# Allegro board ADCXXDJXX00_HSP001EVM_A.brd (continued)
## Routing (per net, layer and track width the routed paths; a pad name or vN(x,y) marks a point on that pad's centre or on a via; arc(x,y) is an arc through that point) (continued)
LMK_LMX_DATA: length 169.4
  TOP w0.279: R119.2 69.34,37.85 69.98,37.21 69.98,29.97 71.37,28.57 77.09,28.57 v1(78.87,30.35)
  L04_SIG-1 w0.14: v1(99.67,94.05) 99.67,92.89 95.43,88.65 85.71,88.65 77.64,96.72 77.64,102.46 68.7,111.4 62.23,111.4 61.32,112.32 v1(61.32,112.89)
  L10_SIG-2 w0.165: v1(61.32,112.89) 61.43,113 62.2,113 62.48,112.72 62.48,112.19 64.73,109.94 64.73,59.02 72.17,51.59 72.17,37.05 v1(78.87,30.35)
  BOTTOM w0.279: U4.20 100.32,97.93 100.32,94.7 v1(99.67,94.05) ; v1(61.32,112.89) 61.3,112.9 U3.17
LMK_SDO: length 119.2
  TOP w0.279: v1(107.44,47.24) 100.84,47.24 94.23,40.64 94.23,35.21 92.78,33.76 75.24,33.76 72.24,36.77 72.24,40.22 70.35,42.11 67,42.11 66.67,41.78 R178.2
  L10_SIG-2 w0.165: v1(104.75,103.96) 104.75,103.22 105.54,102.43 105.54,96.99 105.06,96.51 103.25,96.51 102.65,95.9 102.65,58.34 105.08,55.91 105.08,49.61 v1(107.44,47.24)
  BOTTOM w0.279: U4.5 104.4,104.31 v1(104.75,103.96)
LMX_CLKB: length 27.1
  L04_SIG-1 w0.14: v1(79.48,97.23) 79.78,97.53 v1(79.78,103.42)
  BOTTOM w0.279: C108.2 R52.2 64.32,109.21 69.75,103.78 76.58,103.78 76.94,103.42 v1(79.78,103.42)
LMX_CLKM: length 73.9
  BOTTOM w0.254: C51.1 24.42,72.92 24.85,72.92 arc(25.64,73.25) 25.97,74.04 25.97,74.59 arc(25.8,75.44) 25.32,76.16 23.26,78.21 arc(22.78,78.93) 22.61,79.78 22.61,93.37 arc(23.36,95.17) 25.15,95.91 44.69,95.91 arc(45.91,96.15) 46.94,96.84 53.13,103.03 arc(54.58,105.2) 55.09,107.76 55.09,113.91 arc(55.42,114.7) 56.21,115.03 56.72,115.03 R45.1 57.34,114.88 arc(57.49,114.91) 57.61,114.99 arc(57.77,115.1) 57.96,115.14 U3.22
LMX_CLKP: length 73.9
  BOTTOM w0.254: U3.23 57.98,115.64 arc(57.77,115.68) 57.6,115.79 arc(57.49,115.87) 57.35,115.89 R44.1 56.72,115.74 56.21,115.74 arc(54.91,115.21) 54.38,113.91 54.38,107.76 arc(53.92,105.47) 52.63,103.53 46.44,97.35 arc(45.64,96.81) 44.69,96.62 25.15,96.62 arc(22.85,95.67) 21.9,93.37 21.9,79.78 arc(22.13,78.66) 22.76,77.71 24.81,75.65 arc(25.14,75.16) 25.26,74.59 25.26,74.04 arc(25.14,73.75) 24.85,73.63 24.42,73.63 C50.1
LMX_CSB: length 109.9
  TOP w0.279: v1(79.2,33.03) 75.1,33.03 71.81,36.32 71.81,39.32 R121.2
  L10_SIG-2 w0.165: v1(79.2,33.03) 79.16,33.03 78.2,33.99 78.2,52.52 65.97,64.75 65.97,108 66.65,108.67 66.65,113.19 65.54,114.29 60.13,114.29 v1(58.02,116.4)
  BOTTOM w0.127: U3.24 58.28,116.14 v1(58.02,116.4)
LMX_OSCM: length 46.8
  L10_SIG-2 w0.16: v4(96.88,92.46) 96.83,92.42 96.83,91.76 arc(96.4,90.72) 95.36,90.29 91.46,90.29 arc(89.09,90.76) 87.08,92.1 85.93,93.25 85.88,93.3 85.41,93.77 85.32,93.86 84.83,94.35 84.77,94.41 84.29,94.89 84.04,95.15 83.73,95.45 83.13,96.05 74.19,104.99 74.06,105.12 73.54,105.64 73.48,105.71 73.09,106.09 arc(72.46,107.03) 72.24,108.15 72.24,109.08 arc(72.06,110.01) 71.53,110.79 69.67,112.65 v4(69.61,112.65)
  BOTTOM w0.254: v4(96.88,92.46) 96.85,92.49 96.85,94.36 C151.2 ; U3.9 66.1,115.14 arc(66.27,115.1) 66.41,115.01 arc(66.5,114.95) 66.61,114.92 66.82,114.92 arc(67.33,114.82) 67.76,114.54 69.61,112.69 v4(69.61,112.65)
LMX_OSCP: length 47.3
  L10_SIG-2 w0.16: v4(70.14,113.19) 70.14,113.13 72.01,111.26 arc(72.68,110.26) 72.91,109.08 72.91,108.15 arc(73.08,107.29) 73.57,106.56 73.73,106.4 arc(73.83,106.34) 73.95,106.31 74.3,106.31 arc(74.4,106.29) 74.49,106.24 74.68,106.05 arc(74.74,105.96) 74.76,105.85 74.76,105.5 arc(74.78,105.38) 74.85,105.28 82.96,97.17 arc(83.14,97.05) 83.36,97 83.55,97 arc(83.77,96.96) 83.96,96.84 83.96,96.83 arc(84.11,96.61) 84.17,96.34 84.17,96.16 arc(84.19,96.03) 84.27,95.91 84.41,95.77 arc(84.5,95.71) 84.61,95.69 84.84,95.69 arc(85.04,95.65) 85.2,95.53 85.2,95.53 arc(85.34,95.32) 85.39,95.08 85.39,94.88 arc(85.42,94.75) 85.49,94.64 85.62,94.51 arc(85.73,94.43) 85.86,94.41 86.06,94.41 arc(86.31,94.36) 86.52,94.21 86.57,94.17 arc(86.69,93.98) 86.74,93.77 86.74,93.48 arc(86.75,93.4) 86.8,93.33 87.56,92.57 arc(89.35,91.38) 91.46,90.96 91.94,90.96 arc(92.05,90.98) 92.15,91.04 92.24,91.14 arc(92.46,91.29) 92.72,91.34 92.72,91.34 arc(92.96,91.29) 93.17,91.15 93.29,91.04 arc(93.37,90.98) 93.47,90.96 93.72,90.96 arc(93.82,90.98) 93.91,91.04 93.92,91.05 94.03,91.16 arc(94.19,91.27) 94.39,91.31 arc(94.6,91.27) 94.78,91.15 94.9,91.03 arc(94.97,90.98) 95.07,90.96 95.36,90.96 arc(95.93,91.19) 96.16,91.76 96.16,92.42 v4(96.12,92.46)
  BOTTOM w0.254: v4(70.14,113.19) 70.11,113.19 68.26,115.04 arc(67.6,115.48) 66.82,115.64 U3.8 ; C250.1 96.14,94.36 96.14,92.49 v4(96.12,92.46)
LMX_SDO: length 118
  TOP w0.279: U8.43 v1(66.4,40.37)
  L10_SIG-2 w0.165: v1(78.78,31.79) 76.97,33.6 76.97,40.28 75.99,41.26 75.99,49.44 65.41,60.03 65.41,113.02 64.62,113.8 60.47,113.8 59.77,113.1 58.02,113.1 v1(56.72,111.81)
  BOTTOM w0.279: v1(78.78,31.79) 75.32,31.79 72.62,34.49 67.61,34.49 66.4,35.71 v1(66.4,40.37)
MUX_OUT: length 35.5
  TOP w0.279: v1(57.74,111.81) 57.74,111.08 57.46,110.8 56.76,110.8 56.24,111.32 50.05,111.32 48.56,112.81 48.56,122.49 49.72,123.66 57.87,123.66 v1(59.16,122.37)
  BOTTOM w0.254: R50.2 v1(59.16,122.37)
  BOTTOM w0.279: U3.20 57.75,111.81 v1(57.74,111.81)
NCOA0: length 178.5
  TOP w0.279: R11.1 v1(87.37,40.04)
  L04_SIG-1 w0.102: v1(35.33,76.08) 34.93,75.69 33.55,75.69 33.33,75.91 33.33,77.28
  L04_SIG-1 w0.14: v1(76.05,94.3) 72.13,90.39 56.32,90.39 53.67,93.03 53.67,94.27 45.95,102 45.95,110.45 48.74,113.25 48.74,119.83 J7.2 45.62,120.52 41.51,120.52 40.52,119.53 40.52,112.64 34.22,106.34 32.37,106.34 30.56,104.53 30.56,98.18 32.85,95.89 32.85,79.97 33.33,79.49 33.33,77.28
  L10_SIG-2 w0.165: v1(87.37,40.04) 83.72,43.69 83.72,86.63 v1(76.05,94.3)
NCOA1: length 169.7
  TOP w0.279: R12.1 v1(87.37,38.9)
  L04_SIG-1 w0.102: 34.11,77.44 34.11,76.68 34.3,76.49 35.49,76.49 35.72,76.26 35.72,75.9 35.33,75.5 v1(35.33,75.28)
  L04_SIG-1 w0.14: v1(45.03,79.73) 45.09,79.73 47.03,77.79 47.03,49.53 v1(46.38,48.89) ; 34.11,77.44 34.11,79.44 33.43,80.13 33.43,86.51 34.2,87.27 34.2,88.39 33.45,89.14 33.45,96.45 31.28,98.62 31.28,103.58 32.73,105.03 35.52,105.03 42.75,112.26 42.75,117.08 43.75,118.08 45.73,118.08 J7.4
  L10_SIG-2 w0.102: 34.13,78.21 34.13,75.05 34.29,74.9 34.94,74.9 v1(35.33,75.28)
  L10_SIG-2 w0.165: 34.13,78.21 34.13,78.44 34.04,78.54 34.04,80.24 35.94,82.14 41.22,82.14 43.63,79.73 v1(45.03,79.73)
  BOTTOM w0.279: v1(46.38,48.89) 50.02,52.52 56.64,52.52 57.09,52.97 60.25,52.97 60.7,52.52 89.4,52.52 91.03,50.9 91.03,42.56 v1(87.37,38.9)
NCOB0: length 157.1
  TOP w0.279: R17.1 v1(87.37,37.76)
  L10_SIG-2 w0.102: v1(35.33,70.48) 34.92,70.88 31.94,70.88 31.73,71.09 31.73,77.3 31.56,77.47
  L10_SIG-2 w0.165: 31.56,77.47 31.51,77.52 31.51,78.14 31.98,78.61 31.98,82.42 35.52,85.96 42.38,85.96 45.16,88.73 45.16,101.38 43.96,102.58 43.96,110.8 45.57,112.41 45.57,115.39 J7.6
  BOTTOM w0.279: v1(35.33,70.48) 34.7,69.85 34.7,69.82 34.48,69.6 34.43,69.6 33.83,69 33.83,68.37 34.29,67.91 34.29,61.5 33.21,60.42 33.21,53.46 36.92,49.75 42.55,49.75 44.78,47.52 48.3,47.52 49.87,49.09 53.17,49.09 55.72,51.65 56.98,51.65 57.47,52.14 59.88,52.14 60.37,51.65 89.49,51.65 90.26,50.88 90.26,43.75 86.71,40.2 86.71,38.41 v1(87.37,37.76)
NCOB1: length 166
  TOP w0.279: R18.1 v1(87.37,36.61)
  L10_SIG-2 w0.089: 32.54,77.47 32.53,77.46
  L10_SIG-2 w0.102: v1(35.33,71.28) 34.93,71.68 32.73,71.68 32.53,71.87 32.53,77.25
  L10_SIG-2 w0.165: J7.8 46.84,110.99 45.6,109.75 45.6,105.64 46.86,104.38 46.86,88.99 41.59,83.72 34.16,83.72 32.84,82.4 32.84,77.76 32.54,77.47 ; 32.53,77.46 32.53,77.25
  BOTTOM w0.127: v1(35.33,71.28) 35.27,71.28 34.88,70.88 32.67,70.88 32.52,70.74 32.52,70.32 32.29,70.09 30.8,70.09 30.52,69.8
  BOTTOM w0.279: v1(87.37,36.61) 85.75,38.23 85.75,40.36 87.31,41.92 87.31,46.7 85.45,48.55 76.48,48.55 74.48,50.55 55.79,50.55 51.93,46.68 44.22,46.68 42.91,48 28.63,48 24.88,51.75 24.88,55.83 22.25,58.46 22.25,61.7 25.04,64.48 25.04,65.02 26.61,66.59 28.2,66.59 28.76,67.14 28.76,68.04 30.52,69.8
OSC_M: length 17.6
  L04_SIG-1 w0.124: v1(95.55,94.45) 96.15,94.45 96.41,94.71 96.41,96.17 93.6,98.99 90.27,98.99 89.3,99.96 89.3,101.68 90.35,102.72 91.25,102.72 v2(91.47,102.94)
  BOTTOM w0.152: U4.41 92.71,102.81 92.6,102.7 91.71,102.7 v2(91.47,102.94)
OSC_P: length 17.7
  L04_SIG-1 w0.124: v2(91.47,102.18) 91.23,102.41 90.47,102.41 89.61,101.55 89.61,100.09 90.4,99.29 93.72,99.29 94.32,98.69 94.68,98.69 94.84,98.53 94.84,98.18 95.15,97.87 95.51,97.87 95.67,97.72 95.67,97.35 95.97,97.05 96.33,97.05 96.49,96.89 96.49,96.53 96.72,96.3 96.72,94.71 97.05,94.38 v1(97.49,94.38)
  BOTTOM w0.152: v2(91.47,102.18) 91.71,102.42 92.6,102.42 92.71,102.31 U4.40
OSCI: length 8.4
  TOP w0.152: Y2.2 50.78,44.6 C184.1 50.8,42.85 50.95,42.7 51.56,42.7 51.71,42.85 52.84,42.85 53.41,42.27 53.63,42.27 53.73,42.37 U8.2
OSCINN: length 4.5
  BOTTOM w0.152: C150.2 89.11,104.39 C152.2 90.1,104.39 90.29,104.2 92.6,104.2 92.71,104.31 U4.44
OSCINP: length 4.5
  BOTTOM w0.152: C145.2 89.11,103.73 C146.2 90.1,103.73 90.29,103.92 92.6,103.92 92.71,103.81 U4.43
OSCN: length 2.4
  BOTTOM w0.152: C149.2 86.21,104.39 R88.2 R93.1 87.78,104.44 C150.1
OSCO: length 8.4
  TOP w0.152: Y2.1 50.78,40.49 50.8,40.51 50.8,42.24 50.98,42.42 51.68,42.42 51.83,42.57 52.72,42.57 53.3,41.99 53.61,41.99 53.73,41.87 U8.3
OSCP: length 2.3
  BOTTOM w0.152: C144.2 86.16,103.73 R82.2 R85.1 87.78,103.68 C145.1
OVRA0: length 198.7
  TOP w0.279: v1(95.63,34.8) 95.58,34.85 D12.1 ; v1(55.03,95.67) 54.99,95.63 35.21,95.63 v1(31.75,92.17)
  L04_SIG-1 w0.089: v1(36.12,76.08) 36.12,75.9 35.7,75.48 35.7,75.07 35.49,74.85 32.72,74.85 32.51,75.07 32.51,77.26 32.67,77.42 32.67,77.47
  L04_SIG-1 w0.14: 32.67,77.47 32.67,78.43 32.26,78.84 32.26,86.66 31.75,87.17 v1(31.75,92.17) ; v1(135.25,55.37) 134.36,54.48 131.81,54.48 129.37,52.04 120.82,52.04 119.01,50.23 116.9,50.23 101.47,34.8 v1(95.63,34.8) 95.63,48.87 94.73,49.78 v1(91.71,49.78) 91.27,50.22 91.27,51.92 88.33,54.85 62.88,54.85 v1(59.63,51.6)
  L10_SIG-2 w0.165: v1(55.03,95.67) 55.03,65.33 59.63,60.73 v1(59.63,51.6)
OVRA1: length 116
  L04_SIG-1 w0.14: v1(52.46,94.64) 52.41,94.58 52.41,90.56 v1(41.44,79.59) ; v1(91.71,48.64) 90.43,49.91 90.43,50.92 87.32,54.04 63.87,54.04 60.93,51.09 58.91,51.09 v1(58.44,51.56)
  L10_SIG-2 w0.102: v1(36.12,75.28) 35.73,75.68 35.14,75.68 34.93,75.88 34.93,78.22 34.94,78.22
  L10_SIG-2 w0.165: v1(58.44,51.56) 58.44,59.16 52.46,65.14 v1(52.46,94.64) ; v1(41.44,79.59) 40.47,80.56 35.08,80.56 34.51,79.98 34.51,78.93 34.94,78.5 34.94,78.22
OVRB0: length 289.5
  TOP w0.279: v1(34.6,43.69) 35.52,44.61 38.64,44.61 40.45,46.41 51.9,46.41 56.19,50.7 74.62,50.7 75.88,51.96 81.75,51.96 85.21,48.51 85.21,45.16 86.48,43.88 94.89,43.88 95.7,44.7 95.7,46.7 94.91,47.49 R145.2
  L04_SIG-1 w0.14: v1(139.06,56.64) 136,53.58 134.6,53.58 130.15,49.13 130.15,47.67 115.98,33.49 v1(113.46,33.49)
  L10_SIG-2 w0.165: v1(139.06,56.64) 136.57,54.15 131.22,54.15 129.04,51.96 118.19,51.96 108.37,42.14 108.37,34.61 101.57,27.82 64.5,27.82 60.73,31.59 56.38,31.59 55.88,31.09 42.84,31.09 34.6,39.33 v1(34.6,43.69)
  BOTTOM w0.127: 30.33,70.5 30.71,70.88 31.53,70.88 31.72,71.07 31.72,71.51 31.89,71.68 35.57,71.68 35.73,71.52 35.73,70.89 v1(36.14,70.48)
  BOTTOM w0.279: 30.33,70.5 30.1,70.27 29.33,70.27 21.29,62.24 21.29,57.67 22.81,56.15 22.81,50.98 29.45,44.34 33.94,44.34 v1(34.6,43.69)
OVRB1: length 82.5
  L04_SIG-1 w0.102: v1(36.12,71.28) 35.72,70.88 35.07,70.88 34.92,70.73 34.92,68.46 34.75,68.3
  L04_SIG-1 w0.165: 34.75,68.3 34.59,68.14 34.59,64.73 36.29,63.04 36.29,57.64 40.37,53.55 40.37,49.6 42.39,47.58 47.12,47.58 49.56,50.01 60.76,50.01 64.06,53.31 81.42,53.31 v1(84.39,50.34)
  L10_SIG-2 w0.165: v1(91.71,46.35) 90.82,46.35 86.83,50.34 v1(84.39,50.34)
PD: length 53
  L10_SIG-2 w0.089: 31.05,77.47 31.05,77.33 30.93,77.21 30.93,70.28 31.12,70.09 34.13,70.09 v1(34.52,70.48)
  L10_SIG-2 w0.165: J8.2 32.63,98.48 33.78,97.33 40.9,97.33 42.39,95.84 42.39,89.48 40.18,87.27 34.74,87.27 32.38,84.9 31.81,84.9 30.09,83.19 30.09,82.53 29.84,82.28 29.84,81.5 29.45,81.1 29.45,79.23 29.84,78.84 29.84,78.43 30.14,78.13 30.75,78.13 31.05,77.83 31.05,77.47
  BOTTOM w0.279: J8.2 32.63,98.58 R21.1
PG: length 22.5
  TOP w0.279: SJP4.3 61.79,12.06 60.71,13.15 60.71,14.22 54.1,20.83 v1(48.13,20.83)
  BOTTOM w0.305: v1(48.13,20.83) 48.52,20.44 U16.4
PG_RX1: length 17.5
  TOP w0.279: J26.2 122.76,91.39 134.24,91.39 R104.2 136.32,88.6 v5(136.52,88.39)
PLL2 LOCKED:
  vias: v1(50.08,113.61)
PRSNT_M2C_L: length 3.1
  TOP w0.279: v1(133.99,87.12) 133.99,88.78 133.38,89.39 R106.1
RFOUTB_M: length 3.9
  BOTTOM w0.279: U3.19 60.3,113.17 58.98,111.84 R49.1 C110.1
RFOUTB_P: length 4.1
  BOTTOM w0.279: U3.18 60.8,113.45 60.8,113.44 60.8,112.52 61.08,112.24 61.42,112.24 R48.1 C108.1
RFOUTBM: length 7.7
  TOP w0.279: v1(58.98,109.21) 57.05,109.21 arc(56.48,109.1) 55.99,108.78 55.98,108.78 55.86,108.66 arc(55.43,108.37) 54.94,108.27 J20.1
  BOTTOM w0.279: v1(58.98,109.21) C110.2
STAT 0:
  vias: v1(50.08,119.2)
STAT 1:
  vias: v1(50.08,116.4)
SYNC: length 126.1
  TOP w0.279: R97.1 129.2,69.93 v1(129.47,69.93) ; TP4.1 115.82,49.02 123.57,49.02 R98.1 ; v1(119.2,90.55) 117.92,90.55 111.14,97.33 111.14,100.84 109.04,102.94 v3(107.67,102.94)
  L04_SIG-1 w0.14: v1(129.47,69.93) 129.47,64.44 116.46,51.44 TP4.1 111.22,49.24 107.99,49.24 106.69,50.54 106.69,64.36 109.89,67.55 109.89,77.03 108.09,78.83 108.09,83.42 111.14,86.48 111.14,89.77 111.92,90.55 v1(119.2,90.55)
  BOTTOM w0.279: U4.6 104.03,103.81 105.06,102.79 107.52,102.79 v3(107.67,102.94)
SYNC_N: length 137.7
  TOP w0.254: v2(108.88,52.46) 108.85,52.48 104.17,52.48 arc(102.84,52.75) 101.71,53.5 arc(101.08,53.92) 100.33,54.07 43.43,54.07 arc(38.81,53.15) 34.9,50.54 29.64,45.28 arc(25.09,42.24) 19.73,41.17 12.47,41.17 R36.1
  L04_SIG-1 w0.16: v2(135.25,73.15) 134.96,73.45 132.73,73.45 arc(130.92,73.09) 129.39,72.07 124.49,67.17 arc(123.59,66.57) 122.53,66.36 121.89,66.36 arc(120.8,66.14) 119.88,65.52 114.8,60.44 arc(114.45,59.92) 114.33,59.31 114.33,57.65 arc(114.14,56.68) 113.59,55.86 110.92,53.2 arc(110.16,52.68) 109.26,52.5 108.93,52.5 v2(108.88,52.46)
SYNC_P: length 137.7
  TOP w0.254: v2(108.88,53.22) 108.85,53.2 104.17,53.2 arc(103.11,53.41) 102.21,54 arc(101.35,54.58) 100.33,54.78 43.43,54.78 arc(38.54,53.81) 34.39,51.04 29.13,45.78 arc(24.82,42.9) 19.73,41.88 12.47,41.88 R35.1
  L04_SIG-1 w0.16: v2(108.88,53.22) 108.93,53.17 109.26,53.17 arc(109.9,53.3) 110.45,53.67 113.11,56.33 arc(113.52,56.94) 113.66,57.65 113.66,59.31 arc(113.83,60.18) 114.32,60.91 119.41,66 arc(120.55,66.76) 121.89,67.03 122.53,67.03 arc(123.33,67.19) 124.01,67.64 128.92,72.54 arc(130.66,73.71) 132.73,74.12 134.96,74.12 v2(135.25,74.42)
SYNC_SE: length 186.6
  TOP w0.279: v1(133.99,50.29) 133.48,50.8 R98.2
  L04_SIG-1 w0.165: v1(35.31,48.89) 31.69,52.52 27.79,52.52 19.84,60.46 19.84,72.25 25,77.41 v1(27.18,77.41)
  L10_SIG-2 w0.165: v1(133.99,50.29) 133.35,49.66 119,49.66 116.59,47.24 116.59,35.43 108.08,26.92 88.39,26.92 85.47,24 52.32,24 47.67,28.66 42.47,28.66 32.83,38.3 32.83,46.42 v1(35.31,48.89)
  BOTTOM w0.279: R25.1 v1(27.18,77.41)
SYNCSE: length 3.4
  BOTTOM w0.127: 30.21,76.47 30.93,76.47 v1(31.33,76.08)
  BOTTOM w0.279: R25.2 R26.1 29.66,76.71 29.89,76.47 30.21,76.47
SYS+: length 2.1
  TOP w0.279: U1.K1 30.47,70.53 28.57,70.53 C45.2
SYS-: length 2.1
  TOP w0.279: C47.2 28.57,69.63 30.47,69.63 U1.L1
SYSREF+: length 8.1
  BOTTOM w0.254: R76.1 107.53,96.77 R78.1 107.55,97.45 107.55,99 arc(107.13,100.01) 106.11,100.43 104.44,100.43 104.31,100.31 U4.13
SYSREF-: length 8.1
  BOTTOM w0.254: R77.1 106.86,96.77 R79.1 106.84,97.46 106.84,97.67 arc(106.73,97.94) 106.47,98.05 106.29,98.05 arc(106.07,98.14) 105.97,98.36 arc(106.06,98.56) 106.26,98.64 106.48,98.64 arc(106.73,98.75) 106.84,99 arc(106.62,99.51) 106.11,99.72 104.37,99.72 104.28,99.81 U4.14
SYSREFM: length 136.5
  TOP w0.254: v2(41.18,92.78) 41.2,92.76 52.56,92.76 arc(53.99,92.47) 55.2,91.66 arc(56.07,91.08) 57.09,90.88 93.69,90.88 arc(93.88,90.92) 94.05,91.03 94.23,91.21 94.25,91.23 arc(94.51,91.4) 94.81,91.46 94.98,91.46 arc(95.29,91.4) 95.55,91.23 95.75,91.03 arc(95.91,90.92) 96.11,90.88 96.41,90.88 arc(96.61,90.92) 96.78,91.03 96.96,91.21 96.98,91.23 arc(97.26,91.42) 97.6,91.49 97.65,91.49 arc(97.99,91.42) 98.28,91.23 98.47,91.03 arc(98.64,90.92) 98.84,90.88 99.58,90.88 arc(99.78,90.92) 99.94,91.03 100.12,91.21 100.15,91.23 arc(100.37,91.38) 100.64,91.44 100.94,91.44 arc(101.21,91.38) 101.44,91.23 101.64,91.03 arc(101.81,90.92) 102,90.88 104.52,90.88 arc(106.16,91.56) 106.84,93.19 106.84,93.73 v2(106.81,93.76) ; v2(25.42,69.68) 25.45,69.7 26.96,69.7 arc(27.22,69.65) C47.1
  L10_SIG-2 w0.16: v2(41.18,92.78) 41.13,92.74 37.96,92.74 arc(37.29,92.87) 36.73,93.25 36.15,93.83 arc(34.75,94.76) 33.1,95.09 16.77,95.09 arc(15.33,94.49) 14.73,93.05 14.73,70.32 arc(15.15,69.31) 16.17,68.89 23.08,68.89 arc(23.71,69.01) 24.24,69.36 24.3,69.43 arc(24.63,69.65) 25.02,69.72 25.37,69.72 v2(25.42,69.68)
  BOTTOM w0.254: v2(106.81,93.76) 106.84,93.78 106.84,95.37 R80.1 106.81,95.45 R77.2
SYSREFP: length 136.5
  TOP w0.254: v2(107.58,93.76) 107.55,93.73 107.55,93.19 arc(106.66,91.05) 104.52,90.17 57.09,90.17 arc(55.8,90.43) 54.7,91.16 arc(53.72,91.82) 52.56,92.05 41.2,92.05 v2(41.18,92.02) ; v2(25.42,70.44) 25.45,70.41 26.86,70.41 arc(27.17,70.48) C45.1
  L10_SIG-2 w0.16: v2(25.42,70.44) 25.37,70.39 25.02,70.39 arc(24.37,70.27) 23.83,69.9 23.77,69.84 arc(23.45,69.63) 23.08,69.56 22.55,69.56 arc(22.45,69.58) 22.36,69.64 22.13,69.86 arc(21.98,69.97) 21.79,70 arc(21.62,69.97) 21.47,69.87 21.46,69.87 21.31,69.71 21.25,69.65 21.24,69.64 arc(21.16,69.59) 21.05,69.57 20.8,69.57 arc(20.71,69.58) 20.63,69.64 20.55,69.71 20.38,69.89 arc(20.24,69.98) 20.08,70.01 20.01,70.01 arc(19.82,69.98) 19.67,69.87 19.51,69.71 19.44,69.64 arc(19.36,69.59) 19.26,69.57 19.03,69.57 arc(18.91,69.59) 18.81,69.66 18.6,69.87 arc(18.46,69.97) 18.29,70 18.29,70 arc(18.09,69.96) 17.91,69.84 17.78,69.71 arc(17.61,69.6) 17.4,69.56 16.17,69.56 arc(15.63,69.78) 15.4,70.32 15.4,87.7 arc(15.43,87.83) 15.5,87.93 15.59,88.02 15.59,88.02 15.7,88.13 arc(15.79,88.27) 15.82,88.43 15.82,88.43 arc(15.79,88.62) 15.68,88.77 15.59,88.86 15.59,88.86 15.5,88.96 arc(15.43,89.06) 15.4,89.18 15.4,89.4 arc(15.42,89.51) 15.48,89.6 15.59,89.7 15.59,89.7 15.7,89.81 arc(15.79,89.95) 15.82,90.12 arc(15.79,90.29) 15.69,90.44 15.59,90.54 15.59,90.54 15.49,90.64 arc(15.43,90.74) 15.4,90.86 15.4,93.05 arc(15.8,94.02) 16.77,94.42 27.82,94.42 arc(27.98,94.38) 28.12,94.29 28.18,94.23 arc(28.36,94.11) 28.58,94.07 arc(28.84,94.12) 29.06,94.27 29.11,94.32 arc(29.22,94.39) 29.34,94.42 29.51,94.42 arc(29.66,94.39) 29.79,94.3 29.85,94.24 arc(30.05,94.1) 30.28,94.06 arc(30.51,94.11) 30.71,94.24 30.76,94.29 30.8,94.32 arc(30.9,94.39) 31.02,94.42 31.22,94.42 arc(31.34,94.39) 31.45,94.32 31.52,94.25 arc(31.73,94.11) 31.98,94.06 arc(32.2,94.11) 32.39,94.23 32.49,94.33 arc(32.58,94.39) 32.69,94.42 33.1,94.42 arc(34.49,94.14) 35.67,93.35 36.25,92.77 arc(37.03,92.25) 37.96,92.07 41.13,92.07 v2(41.18,92.02)
  BOTTOM w0.254: R76.2 107.58,95.4 107.55,95.37 ; 107.55,95.37 107.55,93.78 v2(107.58,93.76) ; 107.55,95.37 R81.1
TCRIT1: length 13.5
  TOP w0.279: U2.10 31.28,109.7 v1(31.93,109.06) 32.5,109.63 34.24,109.63 34.67,110.05 34.67,116.35 TP1.1
  BOTTOM w0.279: v1(31.93,109.06) v1(31.93,107.91)
TCRIT2: length 11.2
  TOP w0.279: TP2.1 33.74,113.47 33.74,111.17 33.34,110.77 32.57,110.77 31.99,110.2 R27.2 U2.11
TCRIT3: length 7.4
  TOP w0.279: R29.2 30.28,113.85 28.43,115.69 27.71,115.69 TP3.1
  TOP w0.305: U2.14 30.27,113.24 R29.2
TDI: length 17.9
  BOTTOM w0.102: 128.52,52.32 138.3,52.32 J25.D30
  BOTTOM w0.279: 128.52,52.32 124.39,52.32 123.37,53.34 J27.1
TDIODE+: length 45.4
  L04_SIG-1 w0.124: J17.2 28.44,100.84 28.31,100.97 24.38,100.97 22.48,99.06 22.48,98.63 22.61,98.5 22.87,98.5 22.99,98.38 22.99,98.04 22.87,97.92 22.61,97.92 22.48,97.8 22.48,97.46 22.61,97.34 22.87,97.34 22.99,97.21 22.99,96.88 22.87,96.76 22.61,96.76 22.48,96.63 22.48,83.45 28.11,77.82 28.11,76.21 27.59,75.69 27.59,71.58 27.72,71.46 28.1,71.46 28.34,71.22 28.34,70.82 28.77,70.39 29.51,70.39 29.82,70.7 30.16,70.7 30.47,70.39 31.23,70.39 v1(31.33,70.48)
  BOTTOM w0.152: R40.2 J17.2
TDIODE-: length 45.4
  L04_SIG-1 w0.124: J17.1 28.44,101.4 28.31,101.27 24.26,101.27 22.18,99.19 22.18,83.32 27.81,77.69 27.81,76.34 27.29,75.82 27.29,71.46 27.58,71.16 27.58,71.15 28.65,70.08 31.73,70.08 v1(32.12,70.48)
  BOTTOM w0.152: J17.1 R42.2
TDIODEN: length 26.3
  TOP w0.152: U2.5 25.92,109.7
  TOP w0.279: Q1.2 22.94,109.82 v1(23.55,109.82) C44.2 C46.2 25.19,109.7 25.92,109.7
  BOTTOM w0.152: v1(23.55,109.82) 23.2,109.47 21.65,109.47 21.22,109.04 21.22,107.44 21.84,106.82 22.4,106.82 22.55,106.67 22.55,106.41 22.7,106.26 23.01,106.26 23.16,106.41 23.16,106.67 23.31,106.82 28.29,106.82 30.45,104.66 30.45,101.52 30.19,101.26 29.61,101.26 29.45,101.41 R42.1
TDIODEP: length 25.4
  TOP w0.152: U2.7 v1(26.47,108.17) ; v1(23.67,108.93) 23.8,108.8 C44.1
  BOTTOM w0.152: v1(26.47,108.17) 25.71,108.93 v1(23.67,108.93) 23.41,109.19 21.77,109.19 21.5,108.92 21.5,107.56 21.95,107.1 28.4,107.1 30.73,104.77 30.73,101.4 30.31,100.98 29.61,100.98 29.45,100.83 R40.1
TDO: length 17.4
  BOTTOM w0.102: 128.52,50.8 138.56,50.8 J25.D31
  BOTTOM w0.279: J27.2 128.52,50.8
TMSP+: length 13
  TOP w0.279: R34.1 11.3,46.53 arc(10.91,47.49) 9.96,47.88 J14.1
TMSP-: length 13
  TOP w0.279: R38.1 11.3,36.54 arc(10.91,35.58) 9.94,35.18 J15.1
TMSTP+: length 50.4
  L10_SIG-2 w0.16: v1(12.32,43.05) 12.32,42.02 arc(12.37,41.91) 12.48,41.86 14.16,41.86 arc(18,43.46) 19.6,47.3 19.6,58.98 arc(19.9,60.51) 20.77,61.8 26.55,67.59 arc(27.07,68.36) 27.25,69.27 27.25,72.43 arc(27.11,72.77) 26.77,72.91 26.07,72.91 arc(25.31,73.22) 24.99,73.98 24.99,75.27 arc(25.45,76.36) 26.54,76.81 30.46,76.81 v1(30.52,76.88)
TMSTP-: length 50.4
  L10_SIG-2 w0.16: v1(12.32,40) 12.32,41.03 arc(12.37,41.15) 12.48,41.19 14.16,41.19 arc(18.48,42.98) 20.27,47.3 20.27,58.98 arc(20.52,60.25) 21.24,61.33 27.03,67.12 arc(27.69,68.11) 27.92,69.27 27.92,72.43 arc(27.58,73.24) 26.77,73.58 26.07,73.58 arc(25.78,73.7) 25.66,73.98 25.66,75.27 arc(25.92,75.89) 26.54,76.14 30.46,76.14 v1(30.52,76.08)
U19_BYPASS: length 2.2
  BOTTOM w0.635: R159.2 64.8,14.25 R158.1
V_BUS: length 25.8
  BOTTOM w0.508: 48.01,32.13 46.46,30.59 40.37,30.59 29.84,20.07 v1(29.84,17.4)
  vias: v1(27.43,17.78) v1(27.43,15.62) v1(27.94,16.51) v1(28.45,17.14) v1(28.45,15.62) v1(28.83,16.38) v1(29.84,15.77)
VA11: length 1.3
  BOTTOM w0.279: C60.1 32.82,78.94 C66.1 ; C58.1 v1(28.68,75.23)
  vias: v1(29.9,80.7) v1(30.33,81.92) v1(31.24,81.38) v1(31.19,80.65) v1(31.33,75.28) v1(31.33,71.28) v1(32.12,75.28) v1(32.12,71.28) v1(33.73,76.08) v1(33.73,75.28) v1(33.73,74.48) v1(33.73,73.68) v1(33.73,72.88) v1(33.73,72.08) v1(33.73,71.28) v1(33.73,70.48) v1(63.88,17.65) v1(63.88,16.13) v1(64.01,20.7) v1(65.41,20.83) v1(65.41,16.13) v1(66.93,16.13) v1(67.18,20.95) v1(67.94,17.53) v1(68.07,20.7) v1(68.07,19.05) v1(68.58,16.13) v1(69.34,18.67) v1(69.47,19.91) v1(71.04,17.78) v1(71.12,19.3) v3(69.55,16.03)
VA19: length 7.5
  TOP w0.279: TP32.1 41.96,114.17 v1(42.01,114.12) ; TP14.1 v1(39.12,19.94)
  BOTTOM w0.279: v1(31.17,66.94) 31.19,66.93 31.92,66.93 ; C83.1 32.03,66.93 ; 32.03,66.93 31.92,66.93 ; 32.03,66.93 v1(31.21,67.75) ; 31.92,66.93 v1(31.17,66.18)
  vias: v1(29.26,78.36) v1(29.59,74.62) v1(29.78,71.69) v1(30.43,68.12) v1(30.43,67.31) v1(30.53,66.67) v1(31.01,79.38) v1(31.01,78.59) v1(31.33,74.48) v1(31.33,72.08) v1(32.12,74.48) v1(32.12,72.08) v1(32.93,76.08) v1(32.93,75.28) v1(32.93,74.48) v1(32.93,73.68) v1(32.93,72.88) v1(32.93,72.08) v1(32.93,71.28) v1(32.92,70.46) v1(33.52,103.79) v1(36.96,21.97) v1(37.07,103.79) v1(37.08,24.13) v1(37.08,22.99) v1(37.34,21.08) v1(39.12,18.8) v1(39.12,18.16) v1(39.14,17.27) v1(39.12,16.51) v1(39.12,15.49) v1(39.88,24.51) v1(40.26,15.49) v1(40.39,19.94) v1(40.39,18.16) v1(40.64,20.95) v1(40.81,19.04) v1(41.02,24.13) v1(41.27,23.24) v1(41.4,15.49) v1(42.01,121.74) v1(42.01,119.2) v1(42.01,116.66) v1(42.55,15.39)
VADJ_RX: length 1.7
  TOP w0.279: v3(133.99,38.86) 133.22,38.1 R107.1
  vias: v3(135.25,40.13) v3(136.52,38.86) v3(137.8,40.13)
VBIAS_VCO: length 2.4
  BOTTOM w0.305: C116.2 67.23,118.14 U3.3
VBIASBANK: length 2.6
  BOTTOM w0.127: C111.2 56.77,117.65 v1(56.77,117.62)
  BOTTOM w0.305: U3.27 58.05,117.64 57.69,118 C111.2
VD11: length 1.6
  TOP w0.254: v1(36.92,74.48) v1(37.73,74.48) ; v1(36.92,76.08) v1(37.73,76.08)
  vias: v1(35.33,72.88) v1(35.33,72.08) v1(36.92,72.08) v1(36.93,70.48) v1(37.03,46.43) v1(37.73,72.08) v1(37.73,70.48) v1(37.92,46.31) v1(38.81,46.69) v1(40.31,77.34) v1(40.31,69.34) v1(40.97,68.2) v1(41.02,67.18) v1(45.19,103.19) v3(73.79,18.54) v3(74.8,16.99) v3(75.44,18.52) v3(76.3,15.24) v3(76.45,17.14) v3(76.45,11.56) v3(76.83,18.29) v3(77.34,15.62) v3(78.11,20.32) v3(78.11,18.8) v3(78.11,17.4) v3(78.11,16.38) v3(78.87,11.68)
VIO_B_M2C_RX:
  vias: v5(131.44,38.86) v5(132.72,40.13)
VPHY: length 4.3
  TOP w0.305: U8.4 53.37,41.37 v1(53.21,41.53)
  BOTTOM w0.254: 53.09,41.91 C169.1 C168.1 ; 53.09,41.91 FB12.2 ; 53.09,41.91 53.09,41.66 v1(53.21,41.53)
VREF_VCO1: length 2.5
  BOTTOM w0.305: v1(57.51,120.06) 57.51,119.42 58.29,118.64 U3.29
VREF_VCO2: length 2.8
  TOP w0.381: C115.2 61.52,120.88 v1(62.3,120.88)
  BOTTOM w0.305: U3.36 v1(62.3,120.88)
VREG_VCO: length 1.1
  BOTTOM w0.254: v1(63.38,121.01) 63.3,120.93 U3.38
VREGIN: length 33.1
  TOP w0.305: U8.50 62.31,44.3 62.37,44.35 62.37,44.8 62.04,45.21 v1(62.03,45.21)
  L10_SIG-2 w0.165: JP6.2 46.85,35.83 46.85,38.37 47.9,39.41 47.9,47.2 50.02,49.33 59.94,49.33 61.32,47.95 61.32,45.92 v1(62.03,45.21)
  BOTTOM w0.254: v1(62.03,45.21) C176.1
VTUNE: length 5.7
  BOTTOM w0.254: R55.2 C122.1
  BOTTOM w0.279: U3.35 61.8,121.68 62.2,122.08 64.6,122.08 C122.1
Y1_N: length 11.1
  BOTTOM w0.152: R91.1 84.2,104.41 R92.1 83.21,104.41 83.02,104.22 82.06,104.22 81.02,105.27 81.02,106.16 81.17,106.32 81.26,106.32 81.42,106.47 81.42,106.77 81.26,106.93 81.17,106.93 81.02,107.08 81.02,107.84 81.17,107.99 81.99,107.99 82.15,108.14 Y1.4
Y1_P: length 11.1
  BOTTOM w0.152: R83.1 84.2,103.75 R84.1 83.21,103.75 83.02,103.94 81.94,103.94 80.74,105.15 80.74,107.84 80.58,107.99 79.76,107.99 79.61,108.14 Y1.5
YO1_N: length 0.7
  BOTTOM w0.152: C149.1 R91.2
YO1_P: length 0.7
  BOTTOM w0.152: C144.1 R83.2
N18340257: length 0.5
  BOTTOM w0.254: v1(29.46,7.62) R148.2
N19631466: length 1.7
  TOP w0.279: C235.1 v1(100.15,2.59)
  BOTTOM w0.279: U21.14 100.14,2.61 v1(100.15,2.59)
N19631491: length 1.4
  TOP w0.279: R173.2 v1(103.86,5.82)
  BOTTOM w0.279: v1(103.86,5.82) 103.83,5.79 U21.8
N19631493: length 1.9
  TOP w0.279: R171.2 102.39,2.69 v1(102.23,2.54)
  BOTTOM w0.279: U21.11 102.09,2.69 v1(102.23,2.54)
N19631495: length 1.9
  TOP w0.279: v1(101.47,2.54) 101.27,2.74 R170.2
  BOTTOM w0.279: U21.12 101.44,2.58 v1(101.47,2.54)
N19631505: length 1.5
  TOP w0.279: R172.2 104.07,4.47 v1(104.09,4.49)
  BOTTOM w0.279: U21.10 v1(104.09,4.49)
N19884870: length 7.4
  BOTTOM w0.127: v5(77.07,111.2) 77.07,107.56 v1(77.12,107.51)
  BOTTOM w0.279: v1(77.12,107.51) 77.12,111.14 v5(77.07,111.2)
  vias: v1(77.07,106.5) v1(77.07,105.35) v1(78.08,106.5) v1(78.34,105.35)
N19884947: length 4.1
  BOTTOM w0.279: Y1.2 v1(79.61,122.88)
N19887754: length 2
  TOP w0.254: v1(92.18,103.32) 92.05,103.45 FB8.2
  BOTTOM w0.279: U4.42 92.19,103.31 v1(92.18,103.32)
N19887756: length 9.2
  TOP w0.381: FB9.1 v1(92.18,106.29) 92.18,107 v1(92.05,107.13)
  TOP w0.508: v1(90.65,108.27) 90.25,107.87 90.25,106.98 89.08,105.81 89.08,104.46 89.59,103.96 FB8.1
  BOTTOM w0.279: v1(92.18,106.29) 92.66,105.81 U4.47
  vias: v1(90.65,110.81) v1(90.65,109.42) v1(91.39,110.18)
N19887760: length 3.3
  TOP w0.381: v1(96.24,108.15) C165.1 95.99,107.39 FB10.2
  BOTTOM w0.127: v1(96.24,108.15) 96.24,107.17 U4.53
N19887762: length 3
  TOP w0.381: C166.1 101.7,107.56 101.96,107.81 v1(101.96,108.53)
  BOTTOM w0.279: U4.64 101.77,108.34 v1(101.96,108.53)
N19887789: length 67.2
  L04_SIG-1 w0.14: v1(84.99,119.81) 86.21,118.59 86.21,100.01 89.71,96.52 94.59,96.52 v1(94.92,96.18)
  L10_SIG-2 w0.165: v1(53.82,121.1) 56.38,121.1 56.74,121.46 60.8,121.46 61.96,120.3 68.67,120.3 68.93,120.55 80.21,120.55 80.96,119.81 v1(84.99,119.81)
  BOTTOM w0.279: U4.31 94.77,96.34 v1(94.92,96.18) ; R102.2 52.54,121.1 v1(53.82,121.1)
N19887795: length 66.4
  L04_SIG-1 w0.14: v1(51.65,111.97) 51.21,112.41 51.21,122.48 52.47,123.74 72.39,123.74 75.66,120.47 86.33,120.47 87.62,119.18 87.62,115.36 91.94,111.04 91.94,109.66 v1(93.07,108.53)
  BOTTOM w0.279: v1(93.07,108.53) 93.07,106.69 U4.48 ; v1(51.65,111.97) R103.2
N19887804: length 56
  L10_SIG-2 w0.165: v1(99.27,108.64) 97.77,110.14 95.65,110.14 94.84,110.95 94.84,111.89 93.66,113.07 76.67,113.07 74.44,115.3 64.77,115.3 64.24,114.77 60.3,114.77 59.48,115.59 59.48,116.61 58.23,117.86 57.39,117.86 56.62,118.63 55.3,118.63 54.21,117.54 v1(54.21,117.16)
  BOTTOM w0.279: U4.59 v1(99.27,108.64) ; R101.2 52.42,117.16 v1(54.21,117.16)
N19887822: length 58.5
  L10_SIG-2 w0.165: v1(98.77,107.94) 99.58,107.94 100.29,108.65 100.29,110.04 99.21,111.11 99.21,112.25 97.83,113.64 88.65,113.64 84.36,117.93 66.95,117.93 65.8,119.07 60.13,119.07 59.6,118.54 58.43,118.54 57.47,119.49 54.96,119.49 54.46,118.99 v1(54.46,118.94)
  BOTTOM w0.279: v1(54.46,118.94) 53.91,118.4 52.51,118.4 51.71,119.2 R100.2 ; U4.58 v1(98.77,107.94)
N19887828: length 1.9
  TOP w0.381: C163.1 103.13,100.81 v1(103.51,100.81)
  BOTTOM w0.279: U4.12 v1(103.51,100.81)
N19887830: length 2.3
  BOTTOM w0.279: U4.11 104.01,101.31 v1(104.62,101.92)
N19887836: length 4.1
  TOP w0.381: C154.2 102.73,101.81 v1(103.47,101.81) ; C155.2 v1(93.45,98.24)
  BOTTOM w0.254: v1(92.1,100.18) 92.14,100.18 92.26,100.31 U4.36 ; U4.10 v1(103.47,101.81) ; U4.33 93.45,98.8 v1(93.45,98.24)
N19887876: length 1.8
  TOP w0.279: FB7.2 v1(92.18,101.85)
  BOTTOM w0.254: U4.39 92.25,101.81 92.21,101.85 v1(92.18,101.85)
N19887878: length 3.1
  TOP w0.508: v1(92.09,104.86) 91.48,104.86 90.91,105.44 FB9.2
  BOTTOM w0.254: U4.45 92.14,104.81 v1(92.09,104.86)
N19887910: length 0.9
  BOTTOM w0.279: U4.21 99.77,97.13 v1(99.8,97.1)
N19887912: length 0.9
  BOTTOM w0.279: U4.17 101.77,97.54 v1(102.08,97.23)
N19887930: length 1
  BOTTOM w0.279: U4.26 97.27,97.34 v1(97.51,97.1)
N19955835: length 12.9
  TOP w0.305: U13.4 24.32,13.26 25.02,12.56 25.02,8.51 26.42,7.11 26.42,3.43 26.8,3.05 v1(27.66,3.05)
N20042801: length 1.7
  BOTTOM w0.305: U16.7 51.87,17.36 R155.2
N20043120: length 1.9
  BOTTOM w0.305: R154.2 51.53,18.01 U16.6
N20043460: length 1.7
  BOTTOM w0.305: U16.9 51.89,16.06 R156.2
N20043630: length 1.9
  BOTTOM w0.305: U16.10 51.53,15.41 R157.2
N20101312: length 4.1
  TOP w0.127: 38.52,4.71 38.52,4.7 38.52,3.31
  TOP w0.279: R153.1 R152.2 38.52,3.32 U14.3
N20101373: length 7.5
  TOP w0.127: 38.02,4.71 38.02,4.7 38.02,4.24 38.02,4.24
  TOP w0.279: U14.2 38.02,4.24 37.72,3.94 37.72,1.52 37.97,1.27 39.75,1.27 R150.2
N20111831: length 2.5
  TOP w0.279: R166.1 52.7,3.08 R160.2 52.71,3.49 52.83,3.61 U17.3
N20111884: length 1.6
  TOP w0.279: R164.2 52.33,3.81 U17.2
N20113519: length 2.7
  BOTTOM w0.508: 70.48,3.73 R165.2 ; 70.48,3.73 R169.1 ; 70.48,3.73 71.93,3.73 C216.2
N20150497: length 7.3
  TOP w0.279: SJP2.2 43.31,10.95 43.67,10.58 44.75,10.58 45.21,11.05 45.21,12.83 45.97,13.59 v1(47.24,13.59)
  BOTTOM w0.127: v1(47.24,13.59) 47.24,14.28 U16.14
N20151052: length 3.7
  TOP w0.279: SJP3.2 v1(61.72,10.29)
  BOTTOM w0.279: v1(61.72,10.29) 62.3,9.71 U20.10
N20220969: length 1.6
  TOP w0.279: v1(83.25,2.6) 83.26,2.62 C246.1
  BOTTOM w0.279: U22.14 v1(83.25,2.6)
N20220990: length 1.9
  TOP w0.279: R177.2 v1(87.22,5.82)
  BOTTOM w0.279: v1(87.22,5.82) 87.2,5.79 U22.8
N20220992: length 1.8
  TOP w0.279: R175.2 v1(85.5,2.57)
  BOTTOM w0.279: v1(85.5,2.57) 85.2,2.87 U22.11
N20220994: length 1.9
  TOP w0.279: v1(84.58,2.54) 84.38,2.74 R174.2
  BOTTOM w0.279: U22.12 84.55,2.58 v1(84.58,2.54)
N20221006: length 1.8
  TOP w0.279: R176.2 87.31,4.47 v1(87.33,4.49)
  BOTTOM w0.279: U22.10 v1(87.33,4.49)
N20234062: length 1.7
  TOP w0.279: v1(60.8,120.74) 60.61,120.54 C118.2
  BOTTOM w0.279: U3.33 v1(60.8,120.74)
N20239082: length 5.1
  TOP w0.279: v1(59.03,119.17) 58.11,119.17 57.93,119.35 54.98,119.35 54.64,119.7 R51.2
N20251064: length 0.8
  BOTTOM w0.254: C120.2 R56.1
N20251377: length 1.7
  BOTTOM w0.229: R55.1 C121.1
  BOTTOM w0.254: R54.2 R55.1
N20258125: length 0.8
  TOP w0.381: D2.1 v1(58.5,121.97)
N20381922: length 1.9
  TOP w0.279: U8.14 R130.2
N20381931: length 3.6
  TOP w0.254: v1(52.68,40.39) 52.7,40.37 U8.6
  BOTTOM w0.254: R122.2 53.48,40.39 53.45,40.36 53.03,40.36 53,40.39 v1(52.68,40.39)
N20382261: length 1.4
  BOTTOM w0.356: U20.15 67.39,12.43 C221.1
N20382558: length 3.5
  TOP w0.279: R123.2 79.83,43.39 R131.2 78.97,45.53 U9.4
N20382827: length 6.7
  TOP w0.152: J31.3 9.49,21.34 9.76,21.61 10.76,21.61 11.85,22.69 11.85,24.27 R117.1
N20382847: length 6.7
  TOP w0.152: R116.1 11.57,24.22 11.57,23.92 11.42,23.77 11.32,23.77 11.18,23.64 11.18,23.45 11.32,23.32 11.43,23.32 11.57,23.18 11.57,22.81 10.64,21.89 9.74,21.89 9.49,22.14 J31.2
N20392160:
  vias: v1(8.15,22.94) v1(14.2,16.1) v1(14.83,16.5) v1(14.86,15.75)
N20393078: length 1.7
  TOP w0.279: D7.2 51.97,50.04 v1(52.45,50.52)
N20399374:
  vias: v1(68.71,10.16) v1(69.6,10.16) v1(70.08,9.31) v1(70.61,10.01) v1(70.61,8.53)
N20400206: length 0.2
  BOTTOM w0.254: U20.11 v1(64.55,11.01)
N20442573: length 1.3
  BOTTOM w0.279: J7.1 R13.2
N20442576: length 1.3
  BOTTOM w0.279: J7.3 R14.2
N20442579: length 1.3
  BOTTOM w0.279: J7.5 R15.2
N20442582: length 1.3
  BOTTOM w0.279: J7.7 R16.2
N20446174: length 37.5
  L04_SIG-1 w0.089: 30.1,76.54 30.13,76.5 31.7,76.5 31.75,76.45
  L04_SIG-1 w0.102: 31.75,76.45 v1(32.12,76.08)
  L04_SIG-1 w0.14: v1(25.93,98.88) 29.47,95.35 29.47,88.14 28.79,87.46 28.79,84.88 27.73,83.82 27.73,80.92 29.86,78.8 29.86,76.78 30.1,76.54
  BOTTOM w0.279: TP26.1 18.29,103.33 22.74,98.88 v1(25.93,98.88)
N20447902: length 11
  TOP w0.279: R37.1 39.42,107.91 42.14,105.19 D1.2
N20452911: length 7.1
  TOP w0.152: U2.6 25.98,109.2
  TOP w0.279: Q1.3 20.37,109.31 21.26,108.42 22.43,108.42 Q1.1 22.69,108.16 24.42,108.16 C46.1 25.47,109.2 25.98,109.2
N20475697: length 3.6
  TOP w0.279: R138.1 86.25,40.04 84.94,38.73 U11.14
N20475701: length 3.4
  TOP w0.279: U11.13 85,38.08 85.81,38.9 R139.1
N20475713: length 3.2
  TOP w0.279: U11.12 85.11,37.43 85.43,37.76 R140.1
N20475725: length 3.2
  TOP w0.279: R141.1 85.22,36.61 85.05,36.78 U11.11
N20475883: length 3.1
  TOP w0.279: R142.1 86.34,35.48 U11.9
N20476138: length 5
  TOP w0.279: R142.2 JP8.1
N20477206: length 3.6
  TOP w0.279: U10.14 56.09,28.28 57.4,29.59
N20477210: length 3.4
  TOP w0.279: 57.4,28.45 56.59,27.63 U10.13
N20477222: length 3.2
  TOP w0.279: 57.4,27.3 57.08,26.98 U10.12
N20477234: length 4.8
  TOP w0.279: 57.4,26.16 56.39,26.16 56.22,26.33 v1(55.46,26.33) U10.11
  BOTTOM w0.279: R132.2 53.89,26.33 v1(55.46,26.33)
N20477392: length 3.1
  TOP w0.279: U10.9 54.32,25.02 57.4,25.02
N20477396: length 2.7
  TOP w0.279: R137.2 JP7.1
N20478124: length 0.2
  TOP w0.152: U7.4 v1(67.06,29.4)
N20479286: length 3.6
  TOP w0.279: U12.14 89.38,48.47 R143.1
N20479288: length 3.4
  TOP w0.279: U12.13 89.87,47.82 R144.1
N20479290: length 3.2
  TOP w0.279: R145.1 90.37,47.17 U12.12
N20479292: length 3.2
  TOP w0.279: R146.1 90.52,46.52 U12.11
N20479340: length 3.1
  TOP w0.279: U12.9 90.68,45.22 R147.1
N20479396: length 2.7
  TOP w0.127: JP9.1 93.1,45.21 R147.2
N20523656: length 52.6
  L04_SIG-1 w0.089: 30.1,74.08 33.04,74.08
  L04_SIG-1 w0.102: 33.04,74.08 34.92,74.08 v1(35.33,73.68)
  L04_SIG-1 w0.14: TP25.1 28.92,103.63 29.86,102.69 29.86,98.34 29.17,97.65 28.28,97.65 26.36,99.57 25.07,99.57 24.14,98.64 24.14,94.38 28.24,90.28 28.24,87.17 27.44,86.37 27.44,86.28 26.5,85.33 26.5,83.96 26.88,83.57 26.88,79.52 28.66,77.74 28.66,76.43 29.11,75.98 29.11,74.23 29.25,74.08 30.1,74.08
N20560674:
  vias: v1(139.06,43.94) v1(139.06,41.4) v1(139.06,38.86) v1(140.33,40.13)
N20560927: length 17.5
  TOP w0.279: v1(139.06,88.39) 137.06,86.39 133.62,86.39 133.1,86.91 128.45,86.91 125.44,89.92 J26.1
N20597236: length 2
  TOP w0.279: R108.1 J30.2
N20599204: length 3
  BOTTOM w0.254: U16.5 51.49,19.11 R183.2
N20601243: length 4.5
  TOP w0.279: U15.7 109.15,38.86 109.46,39.17 109.46,40.54 109.98,41.07 D10.1
N20601382: length 3
  TOP w0.279: U15.1 101.96,40.13 101.73,40.37 D11.1
N20601403: length 1.4
  TOP w0.279: R185.1 D10.2
N20601859: length 1.2
  TOP w0.279: R32.1 D11.2
N20602433: length 5.6
  TOP w0.279: D9.2 112.26,36.64 111.94,36.32 R184.1 C14.2 U15.5
N20603216: length 4.4
  TOP w0.279: D12.2 R31.1 C3.2 U15.3
N20603624: length 10.4
  TOP w0.279: U15.2 104.78,38.86 106.05,37.59 U15.6 109.09,37.59 R30.2 C4.2 R33.1
N20606076: length 1.4
  BOTTOM w0.279: J9.1 R20.2
N20606250: length 1.4
  BOTTOM w0.279: R19.2 32.63,103.66 J8.1
N20733419: length 2.2
  TOP w0.279: U8.44 65.25,40.87 R178.1
N198851401: length 0.7
  BOTTOM w0.279: R66.1 88.7,106.5 C131.2
N198852420: length 1
  BOTTOM w0.279: C128.2 94.21,93.97 R63.1
N2037970112: length 1.8
  BOTTOM w0.279: R167.1 61.74,9.06 U20.9

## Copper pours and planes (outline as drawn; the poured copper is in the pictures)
1.4V on TOP: 53.85,2.54 53.85,12.95 58.17,12.95 58.17,8 65.41,8 65.41,2.54 ; 1 cut-out
1.4V on BOTTOM: 54.61,6.22 54.61,13.72 54.1,14.22 54.1,17.02 54.74,17.65 58.17,17.65 58.8,17.02 58.8,14.99 63.37,14.99 63.63,14.73 63.63,10.92 58.8,10.92 58.8,8 62.74,8 62.74,8.51 64.01,8.51 64.01,6.35 64.77,6.35 64.77,5.21 65.53,4.45 65.53,2.54 61.21,2.54 59.94,1.27 50.93,1.27 50.93,2.54
1.4V on L08_PWR-2: 64.01,8.51 64.01,6.35 64.77,6.35 64.77,5.21 65.53,4.45 65.53,2.54 64.42,1.43 51.15,1.43 50.43,2.15 50.43,14.07 51.22,14.86 63.75,14.86 64.13,14.48 64.13,8.64
5.0V_IN on BOTTOM (solid shape): 25.84,2.69 22.03,2.69 22.03,7.21 25.84,7.21
5.0V_IN on TOP: 21.38,11.2 11.35,11.2 11.35,1.36 25.32,1.36 25.75,1.78 25.75,7 24.35,8.4 24.35,9.46 23.28,10.53 22.06,10.53
5.0V_IN on BOTTOM: 6.35,15.11 6.35,1.65 25.78,1.65 25.78,35.05 25.65,35.18 16.51,35.18 16.26,34.92 16.26,17.53 16.26,17.52 16.26,15.78 15.59,15.11
5.0V_IN on L06_PWR-1: 10.79,0.43 25.78,0.43 25.79,0.44 29.34,0.44 30.36,1.46 30.36,46.08 27.3,49.13 14.2,49.13 12.79,47.72 12.79,10.38 10.79,8.39 ; 3 cut-outs
5.0V_IN on L08_PWR-2: 14.28,14.99 3.04,14.99 3.04,1.65 25.78,1.65 25.78,35.18 16.26,35.18 16.26,30.55 14.28,30.55 ; 1 cut-out
5VIN on TOP: 50.69,8.41 50.69,4.92 50.7,4.91 52.06,4.91 52.13,4.98 52.13,6.59 51.96,6.76 51.96,8.41
5VIN on BOTTOM: 95.53,3.07 95.53,3.81 96.04,3.81 96.9,4.67 98.86,4.67 98.86,3.81 100.99,3.81 100.99,1.8 100.51,1.32 97.28,1.32
5VIN on BOTTOM: 79.26,3.92 80.01,4.67 81.97,4.67 81.97,3.81 84.1,3.81 84.1,1.15 83.9,0.95 80.36,0.95 78.3,3.01 78.3,3.71 78.52,3.92
5VIN on BOTTOM: 26.8,3.81 26.8,7.62 25.53,7.62 25.53,10.67 34.42,10.67 35.81,9.27 37.09,9.27 37.51,8.85 37.51,6.93 38.06,6.39 38.06,4.32 35.56,4.32 34.04,5.84 30.23,5.84 30.23,3.81
5VIN on L04_SIG-1: 25.53,11.43 100.97,11.43 100.97,1.27 26.54,1.27 26.54,7.62 25.4,8.76 25.4,11.3 ; 16 cut-outs
5VIN on L08_PWR-2: 26.43,7.62 25.53,7.62 25.53,10.67 25.97,10.67 26.15,10.85 26.15,12.85 27.08,13.79 37.49,13.79 38.37,12.91 38.37,4.05 36.95,2.63 27.24,2.63 26.43,3.44
5VIN on L08_PWR-2: 100.99,3.77 100.99,1.8 100.51,1.32 78.05,1.32 77.01,2.36 77.01,4.14 77.59,4.73 87,4.73 88.55,6.29 88.55,10.51 89.3,11.26 94.88,11.26 95.43,10.72 95.43,7.82 96.45,6.8 98.62,6.8 98.91,6.51 98.91,4.98 99.7,4.19 100.57,4.19
5VIN on L10_SIG-2: 75.38,10.9 80.67,10.9 81.2,11.43 100.97,11.43 100.97,1.27 26.54,1.27 24.47,3.34 24.47,11.4 26.42,13.34 72.94,13.34 ; 16 cut-outs
+2.2V on TOP: 38.99,2.92 38.99,5.03 39.52,5.56 39.52,7.32 39.57,7.37 40.51,7.37 40.51,9.91 40.26,9.91 40.26,13.84 42.04,13.84 42.55,14.35 43.56,14.35 44.2,14.99 44.2,16.26 45.97,16.26 45.97,14.73 46.61,14.73 46.61,14.48 46.48,14.48 46.48,13.84 44.58,13.84 44.58,12.7 43.94,12.7 43.94,11.94 42.42,11.94 42.42,10.03 45.72,10.03 45.72,13.08 47.12,13.08 47.12,10.03 48.01,10.03 48.01,7.37 49.53,7.37 49.53,2.92
+2.2V on L08_PWR-2: 38.99,2.92 38.99,13.1 39.73,13.84 42.15,13.84 43.24,14.93 43.24,16.26 45.97,16.26 49.53,12.7 49.53,2.92
+3.3V_LMX on BOTTOM: 85.72,13.08 85.72,14.48 85.98,14.73 85.98,20.07 86.49,20.07 86.49,20.19 87.12,20.83 87.12,22.23 87.63,22.73 91.31,22.73 91.44,22.61 91.44,19.43 87.76,15.75 87.76,13.08
+3.3V_LMX on L08_PWR-2: 85.98,37.72 83.25,40.45 83.25,66.61 81.28,68.58 81.28,78.99 73.79,86.49 73.79,101.44 65.82,109.41 64.33,109.41 60.58,113.16 58.42,113.16 57.91,113.66 57.91,114.55 57.52,114.94 57.52,117.44 56.51,118.45 55.57,118.45 55.24,118.78 55.24,121.28 56.87,122.91 76.41,122.91 84.75,114.57 84.75,103.2 85.57,102.38 85.57,97.06 85.6,97.03 85.6,87.5 97.66,75.44 97.66,23.85 97.46,23.85 93.9,20.3 93.9,17.91 92.5,16.51 89.53,16.51 88.39,15.37 88.39,13.1 85.72,13.1 85.72,18.92 85.98,19.18
+3.3V_LMXRF on BOTTOM: 80.01,17.78 80.01,21.72 80.64,21.72 81.79,22.86 85.6,22.86 85.72,22.73 85.72,20.45 84.9,19.62 84.9,19.11 83.19,17.4 82.42,17.4 82.04,17.78
+3.3V_LMXRF on L04_SIG-1: 61.02,112.13 61.02,113.73 59.96,114.79 59.96,119.08 59.86,119.18 59.86,120.18 59.36,120.68 52.65,120.68 51.97,120 51.97,106.46 50.27,104.76 50.27,98.46 57.56,91.17 71.63,91.17 76.88,96.41 76.88,102.06 68.22,110.72 62.43,110.72
+3.3V_LMXRF on L08_PWR-2: 75.12,53.21 73.47,54.87 52.94,54.87 51.92,55.89 51.92,110.3 52.04,110.42 52.04,112.46 51.32,113.18 51.32,117.52 52,118.2 56.52,118.2 57.18,117.55 57.18,114.78 57.66,114.3 57.66,113.54 58.8,112.39 60.71,112.39 62.61,110.49 62.61,110.37 72.77,100.21 72.77,85.6 80.14,78.23 80.14,67.31 82.55,64.9 82.55,39.88 85.72,36.7 85.72,20.07 84.84,19.18 84.84,17.53 84.07,16.76 80.9,16.76 79.76,17.91 79.76,22.19 75.12,26.83 ; 3 cut-outs
+3.3VCLK on TOP: 93.38,108.71 93.38,106.81 94.41,106.81 94.41,108.71
+3.3VCLK on TOP: 91.31,93.74 90.59,94.46 81.84,94.46 78.01,98.3 77.45,98.3 77.45,104.36 79.39,104.36 81.31,106.28 81.31,108.69 85.06,112.43 89.76,112.43 89.76,110.2 89.24,110.2 88.19,109.15 88.19,101.87 89.83,100.23 90.62,100.23 91.31,99.54 91.31,96.76 93.6,96.76 94.71,95.65 102.97,95.65 103.31,95.98 103.31,97.53 107.26,101.48 107.26,102.12 107.39,102.25 108.01,102.25 108.14,102.12 108.14,96.91 104.96,93.74
+3.3VCLK on BOTTOM: 102.87,15.37 102.87,16.76 103.12,17.02 103.12,22.13 106.09,22.13 106.17,21.97 108.08,20.07 108.08,17.65 105.79,15.37
+3.3VCLK on L08_PWR-2: 87.12,96.77 87.01,96.89 87.01,102.26 85.87,103.4 85.87,114.33 80.14,120.06 80.14,123.48 108.11,123.48 110.95,120.65 110.95,109.14 111.25,108.84 111.25,97.16 115.82,92.58 115.82,59.69 115.78,59.65 115.78,33.64 110.62,28.47 110.62,17.4 107.82,14.6 104.35,14.6 99.82,19.13 99.82,75.45 87.12,88.15
GND on TOP (solid shape): 25.78,88.54 25.27,88.54 24.34,87.5 25.27,86.46 25.78,86.46 25.78,85.5 25.27,85.5 24.38,84.47 25.27,83.44 25.78,83.44 25.78,81.41 16.64,81.41 16.64,84.96 17.14,84.96 18.03,85.99 17.14,87.02 16.64,87.02 16.64,90.55 25.78,90.55
GND on TOP (solid shape): 25.78,63.14 25.27,63.14 24.34,62.1 25.27,61.06 25.78,61.06 25.78,60.1 25.27,60.1 24.38,59.07 25.27,58.04 25.78,58.04 25.78,56.01 16.64,56.01 16.64,59.56 17.14,59.56 18.03,60.59 17.14,61.62 16.64,61.62 16.64,65.15 25.78,65.15
GND on TOP: 82.55,4.19 82.55,7.11 85.85,7.11 85.85,4.19
GND on TOP: 7,20 7,19.36 9.35,19.36 9.35,20
GND on TOP: 0.98,15.8 0.98,26.81 -0.03,27.82 -0.03,34.15 4.28,34.15 4.28,36.21 -0.03,36.21 -0.03,46.85 5,46.85 5,48.91 -0.03,48.91 -0.03,59.55 4.06,59.55 4.06,61.61 -0.03,61.61 -0.03,72.25 3.56,72.25 3.56,74.31 -0.03,74.31 -0.03,84.95 4.4,84.95 4.4,87.01 -0.03,87.01 -0.03,92.64 0.45,93.12 0.45,112.34 18.36,112.34 18.96,111.73 18.96,107.04 35.4,90.6 35.4,77.15 33.77,75.51 33.77,69.57 35.46,67.87 35.46,57.99 19.51,42.04 19.51,27.82 9.42,27.82 9.42,24.61 3.8,24.61 3.8,17.98 9.34,17.98 9.34,15.8 ; 15 cut-outs
GND on TOP: 94.51,106.32 94.51,106.26 94.14,105.88 94.14,98.49 94.23,98.39 95.19,98.39 95.54,98.74 102.28,98.74 102.45,98.91 102.45,99.54 101.98,100.01 101.98,106.34 94.53,106.34
GND on BOTTOM: 55.58,42.22 55.58,35.31 62.12,35.31 62.12,35.31 63.92,35.31 63.92,36.9 62.12,36.9 62.12,42.22 59.52,42.22 59.52,42.9 58.68,42.9 58.68,42.22
GND on BOTTOM: 28.98,86.59 28.98,83.42 31.66,83.42 31.66,86.59
GND on L02_GND-1: 0.38,0.42 0.38,27.08 0,27.46 0,92.81 0.38,93.2 0.38,125.35 111.76,125.35 111.76,97.15 149.48,97.15 149.48,29.59 111.87,29.59 111.87,0.42 ; 8 cut-outs
GND on L03_GND-2: 0.38,0.42 0.38,27.05 0,27.43 0,92.81 0.38,93.2 0.38,125.35 111.76,125.35 111.76,97.15 149.48,97.15 149.48,29.59 111.92,29.59 111.92,0.42 ; 3 cut-outs
GND on L04_SIG-1: 36.58,76.42 36.58,71.3 35.78,70.51 35.78,66.5 36.29,65.99 41.24,65.99 42.6,67.35 42.6,79.19 41.56,80.23 36.03,80.23 36.02,80.23 35.82,80.23 35.5,79.91 35.5,77.49
GND on L05_GND-3: 0.38,0.42 0.38,27.13 0,27.51 0,92.81 0.38,93.2 0.38,125.35 111.76,125.35 111.76,97.15 149.48,97.15 149.48,29.59 111.92,29.59 111.92,0.42 ; 3 cut-outs
GND on L06_PWR-1: 116.46,96.27 116.46,30.86 149.48,30.86 149.48,96.27
GND on L06_PWR-1: 0.89,15.62 0.89,124.86 111.38,124.86 111.38,84.2 76.71,84.2 76.71,106.81 31.57,106.81 31.57,84.2 11.68,84.2 11.68,15.62
GND on L07_GND-4: 0.38,0.42 0.38,27.03 0,27.41 0,92.81 0.38,93.2 0.38,125.35 111.76,125.35 111.76,97.15 149.48,97.15 149.48,29.59 111.92,29.59 111.92,0.42 ; 3 cut-outs
GND on L08_PWR-2: 2.03,15.49 2.03,31.37 1.91,31.37 1.91,96.77 26.04,96.77 26.04,36.11 15.73,36.11 15.73,31.17 13.21,31.17 13.21,15.49
GND on L08_PWR-2: 117.6,96.39 117.6,30.35 149.1,30.35 149.1,96.39
GND on L09_GND-5: 0.38,0.42 0.38,27.12 0,27.5 0,92.81 0.38,93.2 0.38,125.35 111.76,125.35 111.76,97.15 149.48,97.15 149.48,29.59 111.92,29.59 111.92,0.42 ; 3 cut-outs
GND on L10_SIG-2: 35.7,79.39 35.7,76.38 36.52,75.56 36.52,71.23 35.3,70 35,70 34.52,69.52 34.52,67.56 35.7,66.38 43.72,66.38 44.88,67.53 44.88,78.44 43.63,79.69 36,79.69
GND on L11_GND-6: 0.38,0.42 0.38,27.12 0,27.5 0,92.81 0.38,93.2 0.38,125.35 111.76,125.35 111.76,97.15 149.48,97.15 149.48,29.59 111.92,29.59 111.92,0.42 ; 3 cut-outs
V3P3V on BOTTOM: 97.03,6.98 97.03,9.65 98.68,9.65 98.93,9.91 98.93,14.35 97.03,14.35 97.03,15.87 97.16,16 100.84,16 102.49,14.35 103.25,14.35 103.63,13.97 104.65,13.97 104.65,11.43 101.73,11.43 101.22,10.92 101.22,7.62 98.93,7.62 98.93,6.98
V3P3V on L08_PWR-2: 97.03,6.98 97.03,15.61 98.38,16.97 101.41,16.97 104.41,13.97 104.41,13.53 104.65,13.29 104.65,9.64 101.99,6.98
V3P3V_LMX on BOTTOM: 80.14,6.98 80.14,9.65 81.79,9.65 82.04,9.91 82.04,14.35 80.14,14.35 80.14,16.13 83.82,16.13 85.22,14.73 85.22,12.57 87.76,12.57 87.76,9.14 84.33,9.14 84.33,7.62 82.04,7.62 82.04,6.98
V3P3V_LMX on L08_PWR-2: 80.14,6.98 80.14,9.65 81.79,9.65 82.04,9.91 82.04,14.35 80.14,14.35 80.14,16.13 83.82,16.13 85.34,14.6 85.34,12.83 85.47,12.7 87.76,12.7 87.76,11.43 87.88,11.3 87.88,7.87 87.63,7.62 82.04,7.62 82.04,6.98
V11_OUT on BOTTOM, L08_PWR-2: 71.25,4.7 70.87,5.08 67.18,5.08 67.18,6.35 68.33,6.35 68.33,8.51 69.22,8.51 69.22,7.75 74.3,7.75 74.3,4.7
V19_SNS on BOTTOM: 46.73,19.59 46.73,18.59 46.02,18.59 46.02,17.2 45.98,17.17 44.83,17.17 43.65,18.35 41.86,18.35 41.57,18.65 41.57,22.09 41.83,22.35 42.71,22.35 42.88,22.17 42.88,19.77 43.07,19.59
VBUS on TOP: 18.31,15.01 24.92,15.01 25.02,14.91 25.02,13.58 25.5,13.1 25.5,12.23 26.68,11.05 33.48,11.05 34.39,11.95 34.39,14.62 34.11,14.9 32.74,14.9 32.65,14.81 32.65,13.08 32.47,12.9 31.69,12.9 31.38,13.21 31.38,14.72 31.32,14.77 30.75,14.77 30.62,14.65 30.62,14.04 29.8,13.21 27.61,13.21 27.08,13.74 27.08,15.98 25.93,17.13 18.73,17.13 18.31,16.71
VDDD33 on TOP: 107.59,44.08 107.59,41.57 106.81,40.79 106.81,39.91 106.91,39.81 109.04,39.81 109.06,39.83 109.06,43.85 108.84,44.08
VDDD33 on BOTTOM: 96.9,19.43 96.9,21.97 98.93,21.97 98.93,17.78 98.3,17.78 96.39,15.87 96.39,12.65 95.4,11.66 91.63,11.66 91.63,18.35 92.96,19.68 95.38,19.68 95.63,19.43
VDDD33 on L04_SIG-1: 73.77,45 71.85,45 71.85,48.7 72.95,49.81 74.92,49.81 75.81,48.92 77.98,48.92 78.25,49.18 78.25,52.01 77.77,52.49 64.08,52.49 60.61,49.02 56.9,49.02 56.86,48.98 50.05,48.98 46.21,45.14 46.21,37.01 46.84,36.38 49.6,36.38 50.64,35.34 54.39,35.34 55.24,34.48 55.24,33.53 57.02,31.75 60.96,31.75 64.08,28.63 64.08,17.88 68.8,13.15 105.74,13.15 106.16,13.58 106.16,22.42 94.31,34.27 94.31,40.82 91.75,43.38 87.2,43.38 83.98,40.16 83.98,38.16 82.84,37.02 80.3,37.02 79.76,37.57 79.76,43.02 78.67,44.11 77.09,44.11 76.1,45.11 76.09,45.11 75.65,45.55 74.32,45.55 ; 13 cut-outs
VDDD33 on L06_PWR-1: 45.37,50.25 46.63,51.5 57.73,51.5 61.47,47.76 61.47,37.72 62.1,37.08 62.1,14.36 79.84,14.36 79.84,66.92 78.69,68.07 43.93,68.07 42.16,69.84 42.16,94.96 39.3,97.83 39.3,101.22 41.36,103.28 43.81,103.28 44.61,102.49 73.67,102.49 75.63,100.53 75.63,83.28 76.74,82.17 97.79,82.17 97.85,82.11 107,82.11 111.76,77.34 111.76,59.31 112.14,58.93 112.14,34.16 107.7,34.16 107.7,0.5 34.37,0.5 31.07,3.81 31.07,47.17 34.14,50.25 ; 29 cut-outs
VDDD33 on L08_PWR-2: 91.33,12.05 91.33,14.79 94.89,18.36 94.89,20.19 96.91,22.21 98.57,22.21 98.93,21.85 98.93,18.15 96.64,15.86 96.64,12.02 96.3,11.68 91.7,11.68
VDDD33 on L08_PWR-2: 38.73,105.79 37.21,107.31 26.29,107.31 26.27,107.33 24.87,107.33 23.12,109.08 23.12,111.49 23.45,111.82 23.62,111.82 23.62,120.19 37.08,120.19 40,117.27 40,114.55 42.65,111.91 49.13,111.91 50.46,110.58 50.46,83.15 48.79,81.48 41.29,81.48 38.73,84.04 ; 3 cut-outs
VDDD33 on L10_SIG-2: 73.99,46.79 73.99,44.97 74.76,44.97 74.76,46.79
VDDL19 on TOP: 46.48,20.45 46.48,21.34 46.61,21.46 48.01,21.46 48.01,22.73 52.96,22.73 52.96,28.35 53.26,28.65 54.36,28.65 54.36,29.21 53.44,29.21 53.31,29.34 51.69,29.34 50.67,28.32 50.67,24.77 50.5,24.59 47.8,24.59 46.42,25.97 46.42,26.99 45.59,27.81 42.16,27.81 42.16,20.45
VDDL19 on BOTTOM: 44.96,22.61 44.96,20.45 46.48,20.45 46.48,21.34 46.61,21.46 48.01,21.46 48.01,23.49 53.1,23.49 53.1,27.52 54.76,27.52 54.76,30.42 51.44,30.42 51.44,29.34 49.91,27.81 42.16,27.81 42.16,23.88 45.47,23.88 45.47,22.61
VDDL19 on L04_SIG-1: 87.55,49.46 87.55,45.61 83.51,41.58 83.51,39.06 82.66,38.21 80.6,38.21 80.14,38.67 80.14,40.14 80.16,40.15 80.16,41.75 80.15,41.75 80.15,43.05 78.55,44.66 77.25,44.66 75.84,46.06 74.32,46.06 73.67,45.42 72.44,45.42 72.32,45.54 72.32,48.2 73.37,49.25 74.93,49.25 75.45,48.73 80.54,48.73 81.83,50.02 86.99,50.02
